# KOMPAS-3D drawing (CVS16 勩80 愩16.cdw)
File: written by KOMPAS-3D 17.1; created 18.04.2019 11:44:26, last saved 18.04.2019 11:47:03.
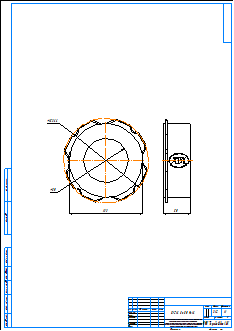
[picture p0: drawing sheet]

Sheet 1: A2, portrait

Title block, sheet 1: name: CVS16 Ду80 Ру16; material: Внимание! Данный продукт является объектом авторского права ООО «Торговый Дом АДЛ». / Запрещается изменение, копирование, распространение / (в том числе путем копирования на другие сайты и ресурсы в Интернете) / или любое иное использование информации и объектов без предварительного / согласия правообладателя (ООО «Торговый Дом АДЛ»).; mass: 3,12; sheets: 1; organisation: ООО "Торговый дом АДЛ"; sheet format: A2

Views: Вид 1, Проекционный вид 2
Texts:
  user
Dimensions and other numbers on the sheet: 133; 80; 50; 153,66; 1:1; 1; 3,12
